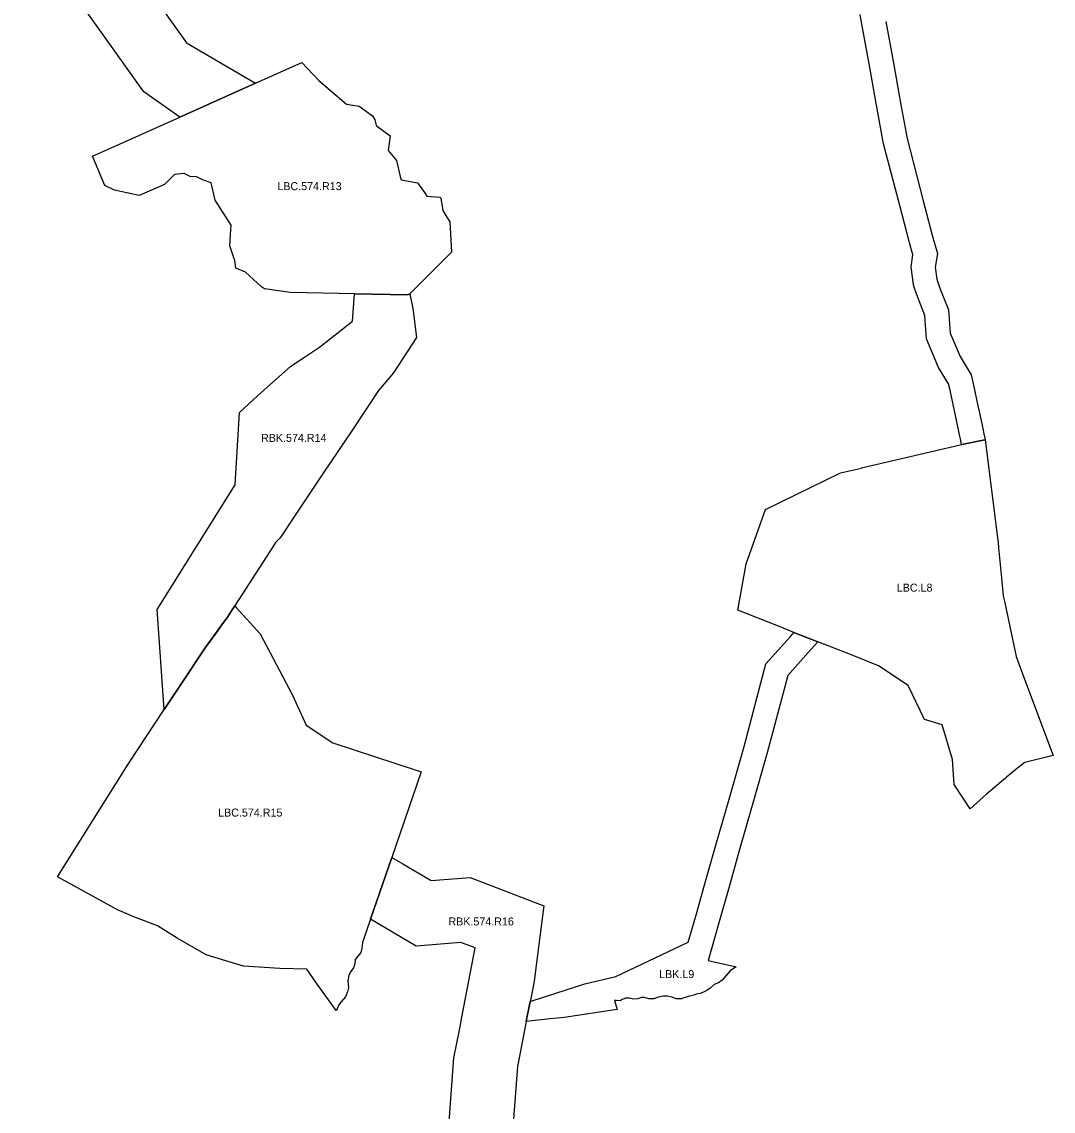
# Model space of a CAD drawing. Extents: x -450188 to -432919, y -1130252 to -1121189.
# Drawn here: x -435551 to -434262, y -1126816 to -1125455 of the extents above; entities that cross this region are included whole.
import ezdxf

# ---------------------------------------------------------------- set-up
doc = ezdxf.new("R2010")
doc.units = 0
for name, color, linetype in [('Vrstva 31', 7, 'Continuous'), ('Vrstva 32', 7, 'Continuous'), ('Vrstva 33', 7, 'Continuous'), ('Vrstva 36', 7, 'Continuous')]:
    doc.layers.add(name, color=color, linetype=linetype)

msp = doc.modelspace()

# ---------------------------------------------------------------- linework, layer by layer
at = {"layer": 'Vrstva 31'}
for p, q in [((-435068.8, -1125796), (-435066.3, -1125794.7)), ((-435321.9, -1126237.1), (-435353.9, -1126285.4)), ((-435353.9, -1126285.4), (-435372.8, -1126313.9)), ((-434914.7, -1126673.3), (-434919.8, -1126699.6)), ((-434919.8, -1126699.6), (-434920.2, -1126701.9)), ((-434920.2, -1126701.9), (-434920.2, -1126701.9))]:
    msp.add_line(p, q, dxfattribs=at)
for points in [[(-435477.7, -1125222.9), (-435468.6, -1125221.4), (-435470.4, -1125304.9), (-435345.1, -1125480.7), (-435258.9, -1125531.3), (-435353.4, -1125573.9), (-435398.3, -1125542.3), (-435550.8, -1125327.8), (-435548.9, -1125234.9), (-435546.1, -1125209.4)], [(-435372.8, -1126313.9), (-435381.6, -1126189.2), (-435284.3, -1126033.2), (-435279, -1125943), (-435256.2, -1125922), (-435214.9, -1125884.9), (-435199.1, -1125874.6), (-435179.1, -1125861.1), (-435137.8, -1125828.7), (-435135.1, -1125794.5), (-435068.8, -1125796)], [(-435066.3, -1125794.7), (-435062.5, -1125812.8), (-435057.9, -1125849.2), (-435086.3, -1125893.5), (-435105.2, -1125915.3), (-435138.7, -1125965.6), (-435173.5, -1126017.6), (-435207.6, -1126068.8), (-435228, -1126099.4), (-435233.8, -1126105.5), (-435237.1, -1126110.7), (-435287.9, -1126189.6), (-435291.9, -1126195.5)], [(-435291.9, -1126195.5), (-435293.9, -1126198.6), (-435302.1, -1126209.8), (-435307.8, -1126217.7), (-435318.2, -1126232), (-435321.9, -1126237.1)], [(-435058, -1126609.8), (-435115.4, -1126576), (-435088.6, -1126499)], [(-435088.6, -1126499), (-435074.9, -1126507), (-435039.3, -1126528), (-434990.7, -1126524), (-434898.5, -1126559.3), (-434904.8, -1126607.6), (-434910.8, -1126653.6), (-434914.7, -1126673.3)], [(-435015.1, -1126950.3), (-435017.7, -1126840.5), (-435011, -1126749.5), (-435003.8, -1126712.6), (-435001.1, -1126698.6), (-434996.5, -1126674.9), (-434984.3, -1126612.1), (-435002.3, -1126605.2), (-435058, -1126609.8)], [(-434920.2, -1126701.9), (-434920.7, -1126704), (-434920.7, -1126704.1), (-434931.6, -1126760.1), (-434937.7, -1126842.4), (-434937.4, -1126853.5), (-434935, -1126953.6), (-434934.8, -1126959.8)]]:
    msp.add_lwpolyline(points, dxfattribs=at)
at = {"layer": 'Vrstva 32'}
for p, q in [((-435353.4, -1125573.9), (-435258.9, -1125531.3)), ((-435068.8, -1125796), (-435135.1, -1125794.5)), ((-434377, -1125983), (-434376.6, -1125982.9)), ((-434376.6, -1125982.9), (-434347.7, -1125977)), ((-434347.7, -1125977), (-434347.4, -1125976.8)), ((-435321.9, -1126237.1), (-435302.1, -1126209.8)), ((-435353.9, -1126285.4), (-435321.9, -1126237.1)), ((-435321.9, -1126237.1), (-435321.9, -1126237.1)), ((-435321.9, -1126237.1), (-435321.9, -1126237.1)), ((-435321.9, -1126237.1), (-435321.9, -1126237.1)), ((-435372.8, -1126313.9), (-435353.9, -1126285.4))]:
    msp.add_line(p, q, dxfattribs=at)
for points in [[(-435258.9, -1125531.3), (-435200.9, -1125505.6), (-435179.6, -1125527.8), (-435145.4, -1125557.6), (-435129.2, -1125560.1), (-435112.8, -1125571.9), (-435109.7, -1125577), (-435108.7, -1125582), (-435108.3, -1125584), (-435090.6, -1125597.1), (-435093, -1125615.4), (-435082.9, -1125628.1), (-435078, -1125648.1), (-435077, -1125651.9), (-435056.6, -1125655.7), (-435047.9, -1125667.8), (-435044.7, -1125672.4), (-435028.7, -1125673.7), (-435027.2, -1125675.2), (-435024.9, -1125690.5), (-435021.9, -1125695.3), (-435016.1, -1125704.4), (-435014, -1125742.5)], [(-435135.1, -1125794.5), (-435215.6, -1125793.1), (-435247.6, -1125788.2), (-435251.6, -1125785.8), (-435271.6, -1125767.6), (-435283.4, -1125762.5), (-435284.7, -1125752.8), (-435286.7, -1125746.9), (-435290.9, -1125734.5), (-435290.1, -1125720.3), (-435289.4, -1125708.7), (-435309.2, -1125677.4), (-435314.2, -1125655.9), (-435323.9, -1125652.5), (-435332.7, -1125648.4), (-435340.4, -1125647.8), (-435348.2, -1125644.2), (-435360.1, -1125645.3), (-435372.5, -1125657.8), (-435383, -1125662.4), (-435394.8, -1125667.6), (-435404.1, -1125671.8), (-435435, -1125665.2), (-435447.1, -1125659), (-435462.7, -1125622.5), (-435440.2, -1125612.5), (-435353.4, -1125573.9)], [(-435014, -1125742.5), (-435066.3, -1125794.7), (-435068.8, -1125796)], [(-434347.4, -1125976.8), (-434347.4, -1125976.9), (-434332, -1126099.7), (-434331.3, -1126105.1), (-434330.6, -1126112.1), (-434326.9, -1126149.7), (-434324.8, -1126172), (-434323.4, -1126178.5), (-434322.9, -1126180.8), (-434308.7, -1126247.7), (-434303.5, -1126261.6), (-434270.6, -1126349.6), (-434262.4, -1126371.5), (-434297.9, -1126380.4), (-434304.7, -1126385.8), (-434320.9, -1126398.6), (-434322.1, -1126399.7), (-434340.6, -1126415.8), (-434345.6, -1126420.1), (-434366.3, -1126438.1), (-434386.2, -1126407.7), (-434388.3, -1126376.7), (-434401, -1126333.2), (-434423, -1126326.4), (-434443.4, -1126284), (-434480.6, -1126259.4), (-434515.7, -1126245.5), (-434556.5, -1126229.4), (-434586.2, -1126217.7), (-434603.5, -1126210.8), (-434644.7, -1126194.5), (-434656.2, -1126189.8), (-434645.8, -1126132.2), (-434621.9, -1126064.2)], [(-434621.9, -1126064.2), (-434528.1, -1126018.3), (-434501.8, -1126012.4), (-434501.8, -1126012.2), (-434385.6, -1125984.8), (-434377, -1125983)], [(-435302.1, -1126209.8), (-435293.9, -1126198.6), (-435287.9, -1126189.6), (-435284.6, -1126184.7), (-435282.6, -1126186.9), (-435252.9, -1126219.7), (-435212.7, -1126296.3), (-435195.6, -1126333.8), (-435162.2, -1126355.6), (-435057.1, -1126390.5), (-435051.8, -1126392.1), (-435088.6, -1126499)], [(-435115.2, -1126576.2), (-435125.2, -1126605.2), (-435126, -1126612.4), (-435127.3, -1126617.6), (-435130.9, -1126622.4), (-435134.2, -1126626.7), (-435135, -1126631.9), (-435136.4, -1126636.9), (-435139.6, -1126641.6), (-435142.1, -1126646.2), (-435143.4, -1126653.3), (-435142.9, -1126662.1), (-435143.8, -1126667), (-435146.6, -1126673.3), (-435151.9, -1126679.5), (-435154.8, -1126683.2), (-435156.7, -1126688), (-435158.1, -1126690.3), (-435182.8, -1126656), (-435194.7, -1126638.7), (-435228.7, -1126637.7), (-435274.1, -1126634.7), (-435295.9, -1126628.4), (-435320.6, -1126620.7), (-435356.7, -1126599.8), (-435381.3, -1126584.6), (-435410.9, -1126573.1), (-435431.5, -1126564.3), (-435506.4, -1126523.4), (-435417.8, -1126382.5), (-435372.8, -1126313.9)], [(-435088.6, -1126499), (-435115.4, -1126576), (-435115.2, -1126576.2)]]:
    msp.add_lwpolyline(points, dxfattribs=at)
at = {"layer": 'Vrstva 33'}
for p, q in [((-434586.2, -1126217.7), (-434556.5, -1126229.4)), ((-434920.7, -1126704.1), (-434915.8, -1126679.1)), ((-434915.8, -1126679.1), (-434915.8, -1126679.1)), ((-434890.9, -1126700.8), (-434920.7, -1126704.1))]:
    msp.add_line(p, q, dxfattribs=at)
for points in [[(-434376.8, -1125983), (-434378.3, -1125975.9), (-434379.4, -1125970.7), (-434379.8, -1125968.9), (-434385, -1125944.6), (-434385.7, -1125941), (-434391.3, -1125914.9), (-434393, -1125906.9), (-434405.6, -1125886.6), (-434420.5, -1125851), (-434422.8, -1125821.5), (-434432.1, -1125798), (-434435.3, -1125788.6), (-434437.1, -1125783.2), (-434440, -1125760.7), (-434437.6, -1125746), (-434442.4, -1125729.1), (-434454.1, -1125684.3), (-434474.4, -1125607.1), (-434483.9, -1125554.2), (-434490.7, -1125516.1), (-434500.9, -1125459.8), (-434503.5, -1125445.3)], [(-434471.4, -1125454.4), (-434462.5, -1125503.9), (-434461.2, -1125510.8), (-434454.4, -1125548.9), (-434453.5, -1125553.9), (-434445, -1125600.6), (-434425.1, -1125676.7), (-434413.4, -1125721.2), (-434406.9, -1125744.3), (-434409.7, -1125761.2), (-434407.7, -1125776.4), (-434406.8, -1125778.9), (-434403.9, -1125787.6), (-434393.3, -1125814.6), (-434390.9, -1125843.9), (-434378.8, -1125872.8), (-434364.8, -1125895.6), (-434362, -1125908.7), (-434356.4, -1125934.7), (-434355, -1125941.5), (-434350.4, -1125962.7), (-434349, -1125969.6), (-434347.4, -1125976.8), (-434347.7, -1125977)], [(-434347.7, -1125977), (-434376.6, -1125982.9), (-434376.8, -1125983)], [(-434915.8, -1126679.1), (-434896.5, -1126672.9), (-434847.4, -1126657.1), (-434808.9, -1126647.6), (-434718.3, -1126604.8), (-434709, -1126572.5), (-434695.4, -1126524.4), (-434683.9, -1126483.8), (-434667.3, -1126426), (-434648.6, -1126360.2), (-434621.2, -1126256.8), (-434590.7, -1126222.7), (-434586.2, -1126217.7)], [(-434556.5, -1126229.4), (-434568.3, -1126242.7), (-434594, -1126271.4), (-434619.7, -1126368.1), (-434638.5, -1126434.2), (-434655, -1126492), (-434666.5, -1126532.6), (-434680.2, -1126580.7), (-434689.4, -1126613), (-434693.6, -1126627.8), (-434658.3, -1126635.9), (-434661.7, -1126637.8), (-434665.9, -1126640.9), (-434671.2, -1126646.9), (-434676, -1126652.2), (-434680.7, -1126655.9), (-434685.8, -1126657.8), (-434691.2, -1126662.7), (-434694.5, -1126664.9), (-434698.5, -1126666.9), (-434703.3, -1126669.2), (-434708.5, -1126669.7), (-434711.5, -1126671.1), (-434715, -1126672), (-434717.9, -1126672.7), (-434722.2, -1126673.9), (-434724, -1126674.3), (-434726.7, -1126675.5), (-434733.3, -1126675.5), (-434738.3, -1126673.5), (-434744.3, -1126672.2), (-434749.5, -1126672.2), (-434755.7, -1126673.5), (-434761.4, -1126675.6), (-434767.7, -1126675.6), (-434772.8, -1126673.9), (-434776.9, -1126673.9), (-434781.4, -1126675.6), (-434786.7, -1126676.2), (-434792.2, -1126675), (-434796.8, -1126675), (-434798.5, -1126675.7), (-434800.8, -1126676.7), (-434803.4, -1126678), (-434808.2, -1126677.6), (-434810.5, -1126677.6), (-434807.2, -1126689.1), (-434873.5, -1126699), (-434890.9, -1126700.8)]]:
    msp.add_lwpolyline(points, dxfattribs=at)

# ---------------------------------------------------------------- texts
at = {"layer": 'Vrstva 36'}
for s, p in [('LBC.574.R13', (-435231.6, -1125665)), ('RBK.574.R14', (-435252, -1125979.6)), ('LBC.L8', (-434457.8, -1126166.8)), ('LBC.574.R15', (-435305.6, -1126447.9)), ('RBK.574.R16', (-435017.9, -1126584)), ('LBK.L9', (-434754.7, -1126649.8))]:
    msp.add_text(s, height=10, dxfattribs=at).set_placement(p)

doc.saveas('drawing.dxf')
